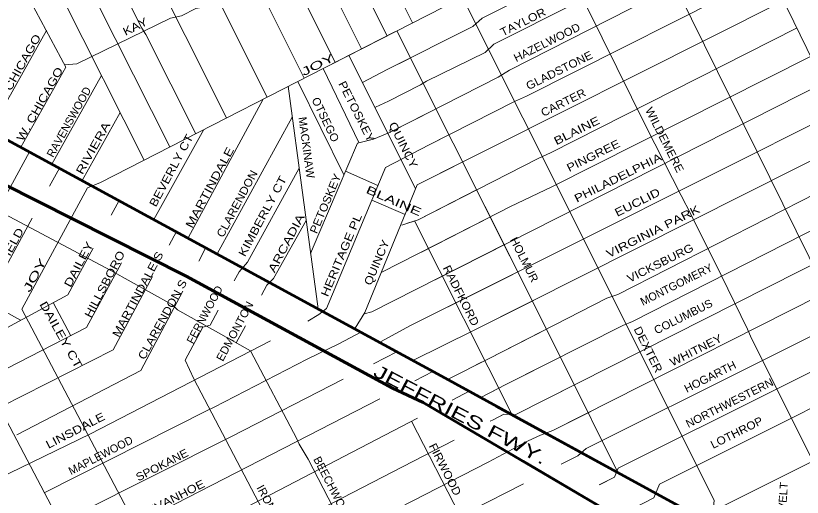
# Model space of a CAD drawing. Extents: x 34705 to 138605, y 34275 to 143551.
# Drawn here: x 76640 to 84007, y 109390 to 113900 of the extents above; entities that cross this region are included whole.
import ezdxf
from ezdxf.enums import TextEntityAlignment as Align

# ---------------------------------------------------------------- set-up
doc = ezdxf.new("R2010")
doc.units = 0
doc.header["$LTSCALE"] = 30
for name, color, linetype, lineweight in [('1', 7, 'Continuous', 13), ('11', 7, 'Continuous', 13), ('51', 7, 'Continuous', 35)]:
    doc.layers.add(name, color=color, linetype=linetype, lineweight=lineweight)

msp = doc.modelspace()

# ---------------------------------------------------------------- linework, layer by layer
at = {"layer": '1'}
for p, q in [((75654.94, 116895.29), (77843.46, 112547.95)), ((78629.96, 116070.99), (79880.02, 113589.59)), ((79244.4, 116068.87), (80355.55, 113832.92)), ((78479.07, 115039.2), (79342.41, 113316.65)), ((78129.46, 114862.98), (78994.02, 113137.99)), ((76926.52, 113762.56), (76402.76, 112825.98)), ((80191.72, 113749.1), (79589.74, 113441.06)), ((79763.12, 113523.5), (80385.38, 112278.58)), ((77108.31, 113418.9), (76688.5, 112668.22)), ((79519.43, 113407.43), (79854.72, 112711.31)), ((77444.1, 113341.26), (76979.25, 112510.03)), ((79190.97, 113238.99), (79472.34, 111153.6)), ((79282.67, 113283.93), (79713.09, 112409.96)), ((78956.03, 113118.51), (78254.15, 111819.36)), ((77619.53, 112992.78), (77263.17, 112355.55)), ((79229.92, 112950.34), (78526.07, 111671.51)), ((78400.43, 112833.58), (77934.73, 111993.03)), ((77048.35, 112472.44), (76956.8, 112304.56)), ((79727.66, 112444.09), (80032.34, 112308.63)), ((77533.28, 112031.26), (77608.81, 112170.24)), ((79975.2, 112172.43), (80287.11, 112039.54)), ((80069.26, 111497.33), (81085.49, 112016.52)), ((80265.51, 112048.74), (80287.11, 112039.54)), ((80440.97, 111687.24), (81085.49, 112016.52)), ((80377.78, 111972.32), (81291.54, 110157.26)), ((78076.66, 111752.52), (78144.23, 111879.12)), ((78354.6, 111602.14), (78421.57, 111728.33)), ((80567.26, 111427.03), (81219.36, 111757.02)), ((80689.94, 111174.26), (81349.63, 111504.49)), ((76991.99, 111213.64), (77155.42, 110903.01)), ((78790.55, 110996.94), (78706.01, 110836.65)), ((79990.71, 110639.56), (80210.75, 110751.85)), ((80377.3, 110481.14), (80547.54, 110568.61)), ((80727.23, 110300.47), (80886.63, 110383.38)), ((80345.99, 110102.17), (81274.92, 108310.06))]:
    msp.add_line(p, q, dxfattribs=at)
at = {"layer": '1', "lineweight": 53}
msp.add_line((81141.26, 110244.39), (82336.58, 109591.28), dxfattribs=at)
for points in [[(35051.57, 135383.85), (35124.2, 135323.83), (40544.24, 132389.75), (44352.38, 130313.49), (48721.15, 127927.26), (52359.24, 125955.06), (53781.74, 125169.15), (55156.63, 124418.97), (56043.46, 123936.71), (56442.24, 123716.41), (57585, 123085.31), (70109.98, 116247.42), (80624.23, 110526.89), (82336.58, 109591.28)], [(81141.26, 110244.39), (85447.32, 107891.61), (90110.84, 105370.56)]]:
    msp.add_lwpolyline(points, dxfattribs=at)
at = {"layer": '1'}
for points in [[(75318.66, 122055.73), (76028.12, 120617.92), (76111.05, 120470.45), (76668.52, 119332.11), (76779.09, 119115.5), (77009.45, 118650.03), (77152.27, 118376.97), (77198.34, 118326.27), (79630.99, 113464.64)], [(80151.24, 121410.3), (81186.58, 119343.85), (81245.62, 119238.86), (81363.7, 118989.51), (81396.49, 118956.7), (82098.39, 117598.39), (84171.26, 113344.68), (84249.98, 113220.01), (85571.75, 110534.58), (85650.47, 110416.46), (86621.31, 108933.49), (87556.79, 106751.11)], [(79390.3, 120990.91), (79448.26, 120959.69), (82465.73, 114945.77), (82478.85, 114867.03), (84804.27, 110153.99), (84994.5, 110114.62), (85486.48, 109123.78), (85899.74, 108388.85), (86044.05, 108047.63), (86318.62, 107420.59)], [(76668.52, 120627.14), (77064.73, 119816.02), (77120.02, 119714.63), (77225.98, 119507.24), (77253.63, 119433.5), (77414.88, 119110.89), (80117.78, 113711.25)], [(79887.23, 113275.2), (80119.73, 113396.54), (80922.13, 113800.46), (81010.14, 113878.14), (83342.03, 115046.33), (83308.36, 115115.43), (84055.39, 115486.05), (84780.15, 115853.73), (85701.62, 116319.79), (88054.48, 117457.76), (90474.63, 118656.58), (90578.17, 118677.29), (92949.15, 119857.99), (93006.09, 119873.52), (93446.12, 120111.73), (93901.23, 120343.43)], [(75038.31, 120098.59), (76295.34, 117560.08), (78615.41, 112943.83)], [(77802.8, 120115.95), (83180.74, 109363.29), (83167.62, 109179.56), (83161.06, 109087.7), (83168.93, 108770.96)], [(77109.54, 119733.85), (77120.02, 119714.63), (77225.98, 119507.24), (77253.63, 119433.5), (77414.88, 119110.89), (80117.78, 113711.25)], [(80689.94, 111174.26), (84354.1, 113008.47), (84340.45, 113036.2), (85786.57, 113764.41), (86732.64, 114246.88), (86797.56, 114251.52), (89104.74, 115382.29), (89387.63, 115549.29), (91500.04, 116586.12), (91615.98, 116651.07), (94572.47, 118142.53)], [(76120.26, 117167.2), (77820.31, 113783.3), (77857.16, 113723.39), (78325.64, 112795.23)], [(80011.01, 113044.4), (80130.08, 113101.36), (80430.34, 113251.54), (80487.28, 113287.79), (81036.02, 113557.07), (81118.85, 113634.75), (83456.37, 114811.7), (83446.25, 114832.46), (84914.74, 115558.55), (84997.57, 115605.16), (85872.45, 116045.33), (86711.1, 116449.25), (88230.66, 117192.95)], [(75002.68, 117047.38), (75203.44, 117047.38), (76258.48, 114973.48), (76309.16, 114908.96), (77108.31, 113418.9)], [(75899.12, 117010.51), (77202.95, 114411.22), (77230.59, 114365.14), (78083.66, 112671.13)], [(79934.57, 112730.59), (79990.31, 112744.05), (80140.43, 112806.19), (81160.27, 113324.04), (81263.8, 113391.36), (83142.99, 114349.38), (83577.59, 114562.94), (83592.46, 114532.43), (85152.88, 115315.16), (86017.4, 115750.16), (87610.05, 116520.54)], [(80081.96, 112426.92), (80104.2, 112479.94), (80513.16, 112692.26), (81310.39, 113096.18), (81424.28, 113147.97), (83706.01, 114299.42), (83734.59, 114240.76), (85220.18, 114994.1), (86146.83, 115449.8), (86290.06, 115480.49), (86959.58, 115817.48)], [(82723.94, 109035.34), (90363.22, 112867.13), (94388.72, 114894.36), (95824.19, 115602.97)], [(83225.22, 115286.03), (82493.18, 114911.99), (81871.6, 114608.68), (79589.74, 113441.06)], [(80822.99, 110900.14), (80927.58, 110951.99), (84485.1, 112742.32), (84518.22, 112675.03), (86008.47, 113424.93), (85980.22, 113482.88), (86885.68, 113936.06), (87010.89, 113945.34), (89277.36, 115059.84)], [(81719.55, 114530.87), (82544.45, 112860.75), (82872.43, 112217.69), (82964.27, 112040.52), (83246.34, 111469.63), (83495.61, 110964.37), (83521.85, 110898.75), (84105.35, 109728.24)], [(77097.09, 113439.81), (77210.9, 113448.57), (78088.16, 113876.76), (78193.85, 113897.91), (78325.97, 113966.63), (78410.52, 113982.49), (78722.31, 114146.37), (79177.36, 114371.22)], [(80567.26, 111427.03), (84216.19, 113273.53), (84187.69, 113318.66), (85872.37, 114183.09)], [(80279.25, 112020.44), (80400.57, 112315.53), (83832.01, 114040.85)], [(80209.84, 113758.36), (81796.64, 110596.91), (82272.34, 109635.94)], [(80310.6, 111955.83), (80410.93, 111989.28), (81534.29, 112564.1), (81648.18, 112615.88), (83954.45, 113783.63)], [(80191.72, 113749.1), (77433.37, 112337.65), (77312.09, 112287.1), (76696.16, 111150.61), (78644.99, 107452.17), (78682.72, 107362.96)], [(79887.23, 113275.2), (80119.73, 113396.54), (80321.26, 113497.99)], [(80440.97, 111687.24), (81275.45, 112113.57), (81661.12, 112298.7), (84083.87, 113519.52)], [(80011.01, 113044.4), (80130.08, 113101.36), (80430.34, 113251.54), (80443.93, 113260.19)], [(79402.31, 111672.64), (79477.8, 111858.52), (79840.18, 112707.8), (79990.31, 112744.05), (80140.43, 112806.19), (80566.52, 113022.55)], [(79934.57, 112730.59), (79990.31, 112744.05), (80140.43, 112806.19), (80566.52, 113022.55)], [(81081.38, 110367.76), (81231.34, 110446.33), (82325.8, 110998.38), (82418.55, 111035.49), (84742.28, 112219.81), (84723.33, 112258.31), (86213.7, 113003.84)], [(79376.36, 111038.37), (79477.8, 111102.46), (79550.28, 111159.43), (80104.2, 112479.94), (80513.16, 112692.26), (80690.54, 112782.13)], [(80081.96, 112426.92), (80104.2, 112479.94), (80513.16, 112692.26), (80690.54, 112782.13)], [(75455.17, 112634.83), (76428.94, 112098.84), (77530.06, 111513.54), (78101.34, 111195.54), (78156.63, 111144.85), (78838.49, 110762.33), (79271.56, 109937.38), (79294.6, 109886.69), (79379.38, 109747.16), (80363.34, 107847.51), (80366.86, 107839.75)], [(76769.59, 112624.1), (75631.9, 110537.66), (75811.58, 110168.97)], [(79820.77, 110974.3), (79908.77, 111119.3), (80400.57, 112315.53), (80821.95, 112527.4)], [(80279.25, 112020.44), (80400.57, 112315.53), (80821.95, 112527.4)], [(79294.31, 112473.12), (78810.85, 111591.89), (78731.3, 111501.18), (78685.33, 111416.39)], [(80953.93, 110630.36), (81066.71, 110687.56), (82177.4, 111253.53), (82279.43, 111290.64), (84606.32, 112475.92)], [(80255.62, 111937.5), (80410.93, 111989.28), (80955.73, 112268.06)], [(80310.6, 111955.83), (80410.93, 111989.28), (80955.73, 112268.06)], [(82417.02, 109281.16), (82437.1, 109291.2), (82617.97, 109383.98), (82668.98, 109513.88), (85402.17, 110879.1), (85371.53, 110941.37), (87872.4, 112171.46)], [(81034.18, 112115.98), (81796.64, 110596.91), (82272.34, 109635.94)], [(76792.46, 112003.16), (76161.73, 110846.44), (77940.09, 107470.6), (77986.16, 107360), (77991.01, 107350.74)], [(79360.35, 111983.63), (79053.09, 111439.28), (78991.24, 111377.4), (78942.11, 111284.27)], [(81185.07, 110154.13), (81212.79, 110167.99), (81319.45, 110163.35), (84870.76, 111958.78)], [(75163.87, 111836.73), (75255.78, 111821.41), (75298.05, 111815.37), (76685.65, 111048.29)], [(75212.85, 110253.29), (77129.23, 111287.72), (77365.61, 111722.71)], [(79902.68, 111109.72), (79976.88, 111128.27), (81219.36, 111757.02)], [(81328.64, 109858.33), (81440.03, 109917.48), (81555.97, 109973.14), (81671.9, 110014.9), (84999.02, 111698.19)], [(76348.66, 110491.59), (77304.3, 110978.94), (77631.51, 111584.89)], [(80057.5, 110844.51), (80338.61, 110998.38), (81349.63, 111504.48)], [(76507.27, 110241.55), (77553.09, 110771.55), (77919.49, 111458.06)], [(81755.22, 109701.96), (81903.78, 109778.3), (81982.62, 109847.89), (85135.56, 111420.79)], [(76650.09, 109974.25), (77811.09, 110577.98), (78205.13, 111320.5)], [(80360.03, 110670.63), (80927.58, 110951.99), (81488.91, 111234.49)], [(80822.99, 110900.14), (80927.58, 110951.99), (81488.91, 111234.49)], [(78537.59, 111143.84), (78460.7, 111001.98), (78391.6, 110983.55), (78225.74, 110674.77), (78308.67, 110499.64), (79825.45, 107604.72), (79816.34, 107554.61)], [(82114.55, 109510.27), (82246.96, 109578.82), (82284.06, 109662.33), (85268.4, 111150.89)], [(80690.94, 110496.97), (81066.71, 110687.56), (81624.44, 110971.76)], [(80953.93, 110630.36), (81066.71, 110687.56), (81624.44, 110971.76)], [(76906.82, 109431.54), (78432.57, 110201.62), (78497.5, 110234.09), (79369.36, 110684.08), (79666.16, 110827.9), (79872.15, 110936.07)], [(73935.18, 109006.07), (75183.97, 109043.02), (75480.77, 109047.66), (76287.71, 109460.53), (76371.18, 109516.2), (76793.2, 109720.32), (77340.43, 109984.75), (79025.46, 110855.54)], [(80996.51, 110323.28), (81231.34, 110446.33), (81758.36, 110712.16)], [(81081.38, 110367.76), (81231.34, 110446.33), (81758.36, 110712.16)], [(77050.58, 109148.55), (77212.89, 109232.06), (78659.81, 109960.39), (79707.27, 110494.92)], [(81084.43, 110103.14), (81110.76, 110116.96), (81212.79, 110167.99), (81319.45, 110163.35), (81892.11, 110452.88)], [(81185.07, 110154.13), (81212.79, 110167.99), (81319.45, 110163.35), (81892.11, 110452.88)], [(77203.62, 108860.93), (77741.58, 109139.27), (77801.87, 109157.83), (80051.43, 110313.7)], [(77358.98, 107809.02), (77669.7, 107971.39), (77762.45, 108022.42), (81064.38, 109718), (81440.03, 109917.48), (81555.97, 109973.14), (81671.9, 110014.9), (82025.71, 110193.91)], [(81328.64, 109858.33), (81440.03, 109917.48), (81555.97, 109973.14), (81671.9, 110014.9), (82025.71, 110193.91)], [(75800.37, 107755.23), (76032.64, 107883.25), (76088.29, 107906.45), (77901.58, 108834.26), (77961.87, 108862.09), (80403.28, 110131.97)], [(77201.62, 108100.95), (77335.79, 108175.51), (77618.69, 108314.68), (78184.47, 108602.31), (80739.76, 109922.11), (80746.98, 109925.91)], [(81750.26, 109699.41), (81903.78, 109778.3), (81982.62, 109847.89), (82158.85, 109935.81)], [(81755.15, 109701.92), (81903.78, 109778.3), (81982.62, 109847.89), (82158.85, 109935.81)], [(82105.72, 109505.71), (82246.96, 109578.82), (82284.06, 109662.33), (82296.68, 109668.63)], [(77825.05, 107688.41), (78363.01, 107957.48), (78455.76, 108017.78), (81395.26, 109516.98)]]:
    msp.add_lwpolyline(points, dxfattribs=at)
at = {"layer": '51', "lineweight": 60}
for points in [[(67942.15, 119618.13), (70194.46, 119620.82), (71080.59, 119480.93), (71991.18, 119251.97), (72371.35, 118958.42), (72513.07, 118739.92), (72699.81, 118466.38), (72873.22, 118232.88), (72986.6, 117952.66), (73093.32, 117545.69), (73133.33, 116251.38), (73093.32, 116131.29), (73053.3, 115824.39), (73073.31, 115577.54), (73140, 115243.96), (73300.07, 114723.56), (73666.9, 113989.68), (74218.8, 113487.65), (77177.29, 111994.8), (78236.88, 111462.14), (80168.01, 110411.99), (80456.46, 110276.91), (82330.6, 109176.08), (82543.51, 108967.12)], [(81392.26, 109727.24), (82330.6, 109176.08), (82684.09, 108829.15), (83879.08, 108261.49), (84476.11, 108016.68), (84955.05, 107731.66), (86008.84, 106604.15), (86475.71, 105436.6), (87689.56, 102647.83), (88119.74, 101652.09), (89397.64, 100005.46)], [(81392.26, 109727.24), (82330.6, 109176.08), (82543.51, 108967.12)]]:
    msp.add_lwpolyline(points, dxfattribs=at)

# ---------------------------------------------------------------- texts
at = {"layer": '11'}
for s, height, rotation, width, p in [('TAYLOR', 75, 26.54, 1.15, (81407.57, 113807.2)), ('KAY', 75, 26.464, 1.2, (77775.5, 113765.29)), ('HAZELWOOD', 75, 26.539, 1.05, (81632.16, 113616.58)), ('W. CHICAGO', 75, 60.688, 1.25, (76690.79, 113362.83)), ('JOY', 75, 26.754, 1.7, (79485.27, 113408.12)), ('GLADSTONE', 75, 26.539, 1.1, (81747.5, 113354.73)), ('W. CHICAGO', 75, 60.688, 1.25, (76897.78, 113054.36)), ('PETOSKEY', 75, 296.713, 1.15, (79799.4, 112986.64)), ('CARTER', 75, 26.538, 1.1, (81784.86, 113053.71)), ('OTSEGO', 75, 295.77, 1.05, (79507.38, 112911.29)), ('WILDEMERE', 75, 296.808, 1.1, (82683.76, 112720.64)), ('MACKINAW', 75, 277.684, 1.05, (79326.77, 112660.97)), ('BLAINE', 75, 26.538, 1.3, (81911.25, 112790.22)), ('RIVIERA', 75, 60.69, 1.35, (77396.76, 112642.24)), ('QUINCY', 75, 296.768, 1.2, (80236.87, 112672.46)), ('BEVERLY CT', 75, 61.867, 1.2, (78129.25, 112433.06)), ('PINGREE', 75, 26.539, 1.2, (82065.96, 112556.26)), ('MARTINDALE ', 75, 61.867, 1.3, (78498.03, 112290.11)), ('PHILADELPHIA', 75, 26.539, 1.25, (82297.82, 112349.31)), ('CLARENDON', 75, 61.867, 1.1, (78745.81, 112121.5)), ('PETOSKEY', 75, 67.115, 1.1, (79575.24, 112126.63)), ('KIMBERLY CT', 75, 61.866, 1.25, (78984.12, 112005.02)), ('BLAINE  ', 75, 336.26, 1.55, (80205.88, 112115.09)), ('EUCLID', 75, 26.654, 1.25, (82478.93, 112119.29)), ('VIRGINIA PARK', 75, 26.654, 1.3, (82624.91, 111846.54)), ('ARCADIA ', 75, 61.865, 1.35, (79215.66, 111768.29)), ('HERITAGE PL', 75, 67.168, 1.25, (79724.47, 111643.57)), ('WHITFIELD', 75, 61.377, 1.25, (76557.63, 111589.69)), ('DAILEY', 75, 62.179, 1.3, (77262.57, 111554.21)), ('QUINCY', 75, 67.12, 1.15, (80055.56, 111574.63)), ('HOLMUR', 75, 296.77, 1.05, (81369.8, 111598.88)), ('HILLSBORO', 75, 62.286, 1.2, (77505.82, 111368.56)), ('MARTINDALE S', 75, 61.791, 1.2, (77815.93, 111273.91)), ('VICKSBURG', 75, 26.654, 1.15, (82693.9, 111550.64)), ('JOY', 75, 61.375, 1.75, (76850.55, 111452.4)), ('RADFKORD', 75, 296.768, 1.1, (80777.43, 111262.28)), ('CLARENDON S', 75, 61.198, 1.15, (78046.81, 111036.89)), ('DAILEY CT', 75, 299.283, 1.35, (77030.8, 110893.92)), ('EDMONTON', 75, 61.865, 1.05, (78724.8, 110927.32)), ('COLUMBUS', 75, 26.654, 1.05, (82909.14, 111048.72)), ('DEXTER', 75, 296.602, 1.15, (82530.37, 110757.62)), ('WHITNEY', 75, 26.654, 1.15, (83027.52, 110734.71)), ('HOGARTH', 75, 26.654, 1.05, (83160.77, 110486.08)), ('JEFFRIES FWY.', 120, 332.25, 1.5, (80777.18, 110111.41)), ('NORTHWESTERN', 75, 26.654, 1.05, (83342.41, 110240.35)), ('LINSDALE', 75, 27.4, 1.25, (77215.13, 109982.62)), ('LOTHROP', 75, 26.654, 1.1, (83409.43, 109962.39)), ('FIRWOOD', 75, 297.028, 1.1, (80628.63, 109634.49)), ('SPOKANE', 75, 27.031, 1.1, (78026.54, 109659.71)), ('IVANHOE', 75, 27.03, 1.2, (78177.17, 109368.72)), ('IRONWOOD', 75, 297.579, 1.05, (79032.4, 109214.37)), ('ROOSEVELT', 75, 85.859, 1.05, (83850.77, 109207.82))]:
    msp.add_text(s, height=height, rotation=rotation, dxfattribs=dict(at, width=width)).set_placement(p, align=Align.CENTER)
for s, rotation, p in [('RAVENSWOOD', 60.687, (77170.68, 112886.72)), ('MONTGOMERY', 26.654, (82844.37, 111348.88)), ('FERNWOOD', 61.865, (78442.47, 111082.62)), ('MAPLEWOOD', 27.401, (77452.26, 109749.2)), ('BEECHWOOD', 297.458, (79579.03, 109450.6))]:
    msp.add_text(s, height=75, rotation=rotation, dxfattribs=at).set_placement(p, align=Align.CENTER)

doc.saveas('drawing.dxf')
